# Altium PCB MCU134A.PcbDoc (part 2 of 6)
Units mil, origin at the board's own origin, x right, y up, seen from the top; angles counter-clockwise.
Board outline 4163.98 x 2693.8 mil, 6 copper layers (Top Layer, GND1, SIG1, PWR, GND2, Bottom), stack 58.132 mil thick; 218 components, 287 nets, 1260 pads, 770 vias.
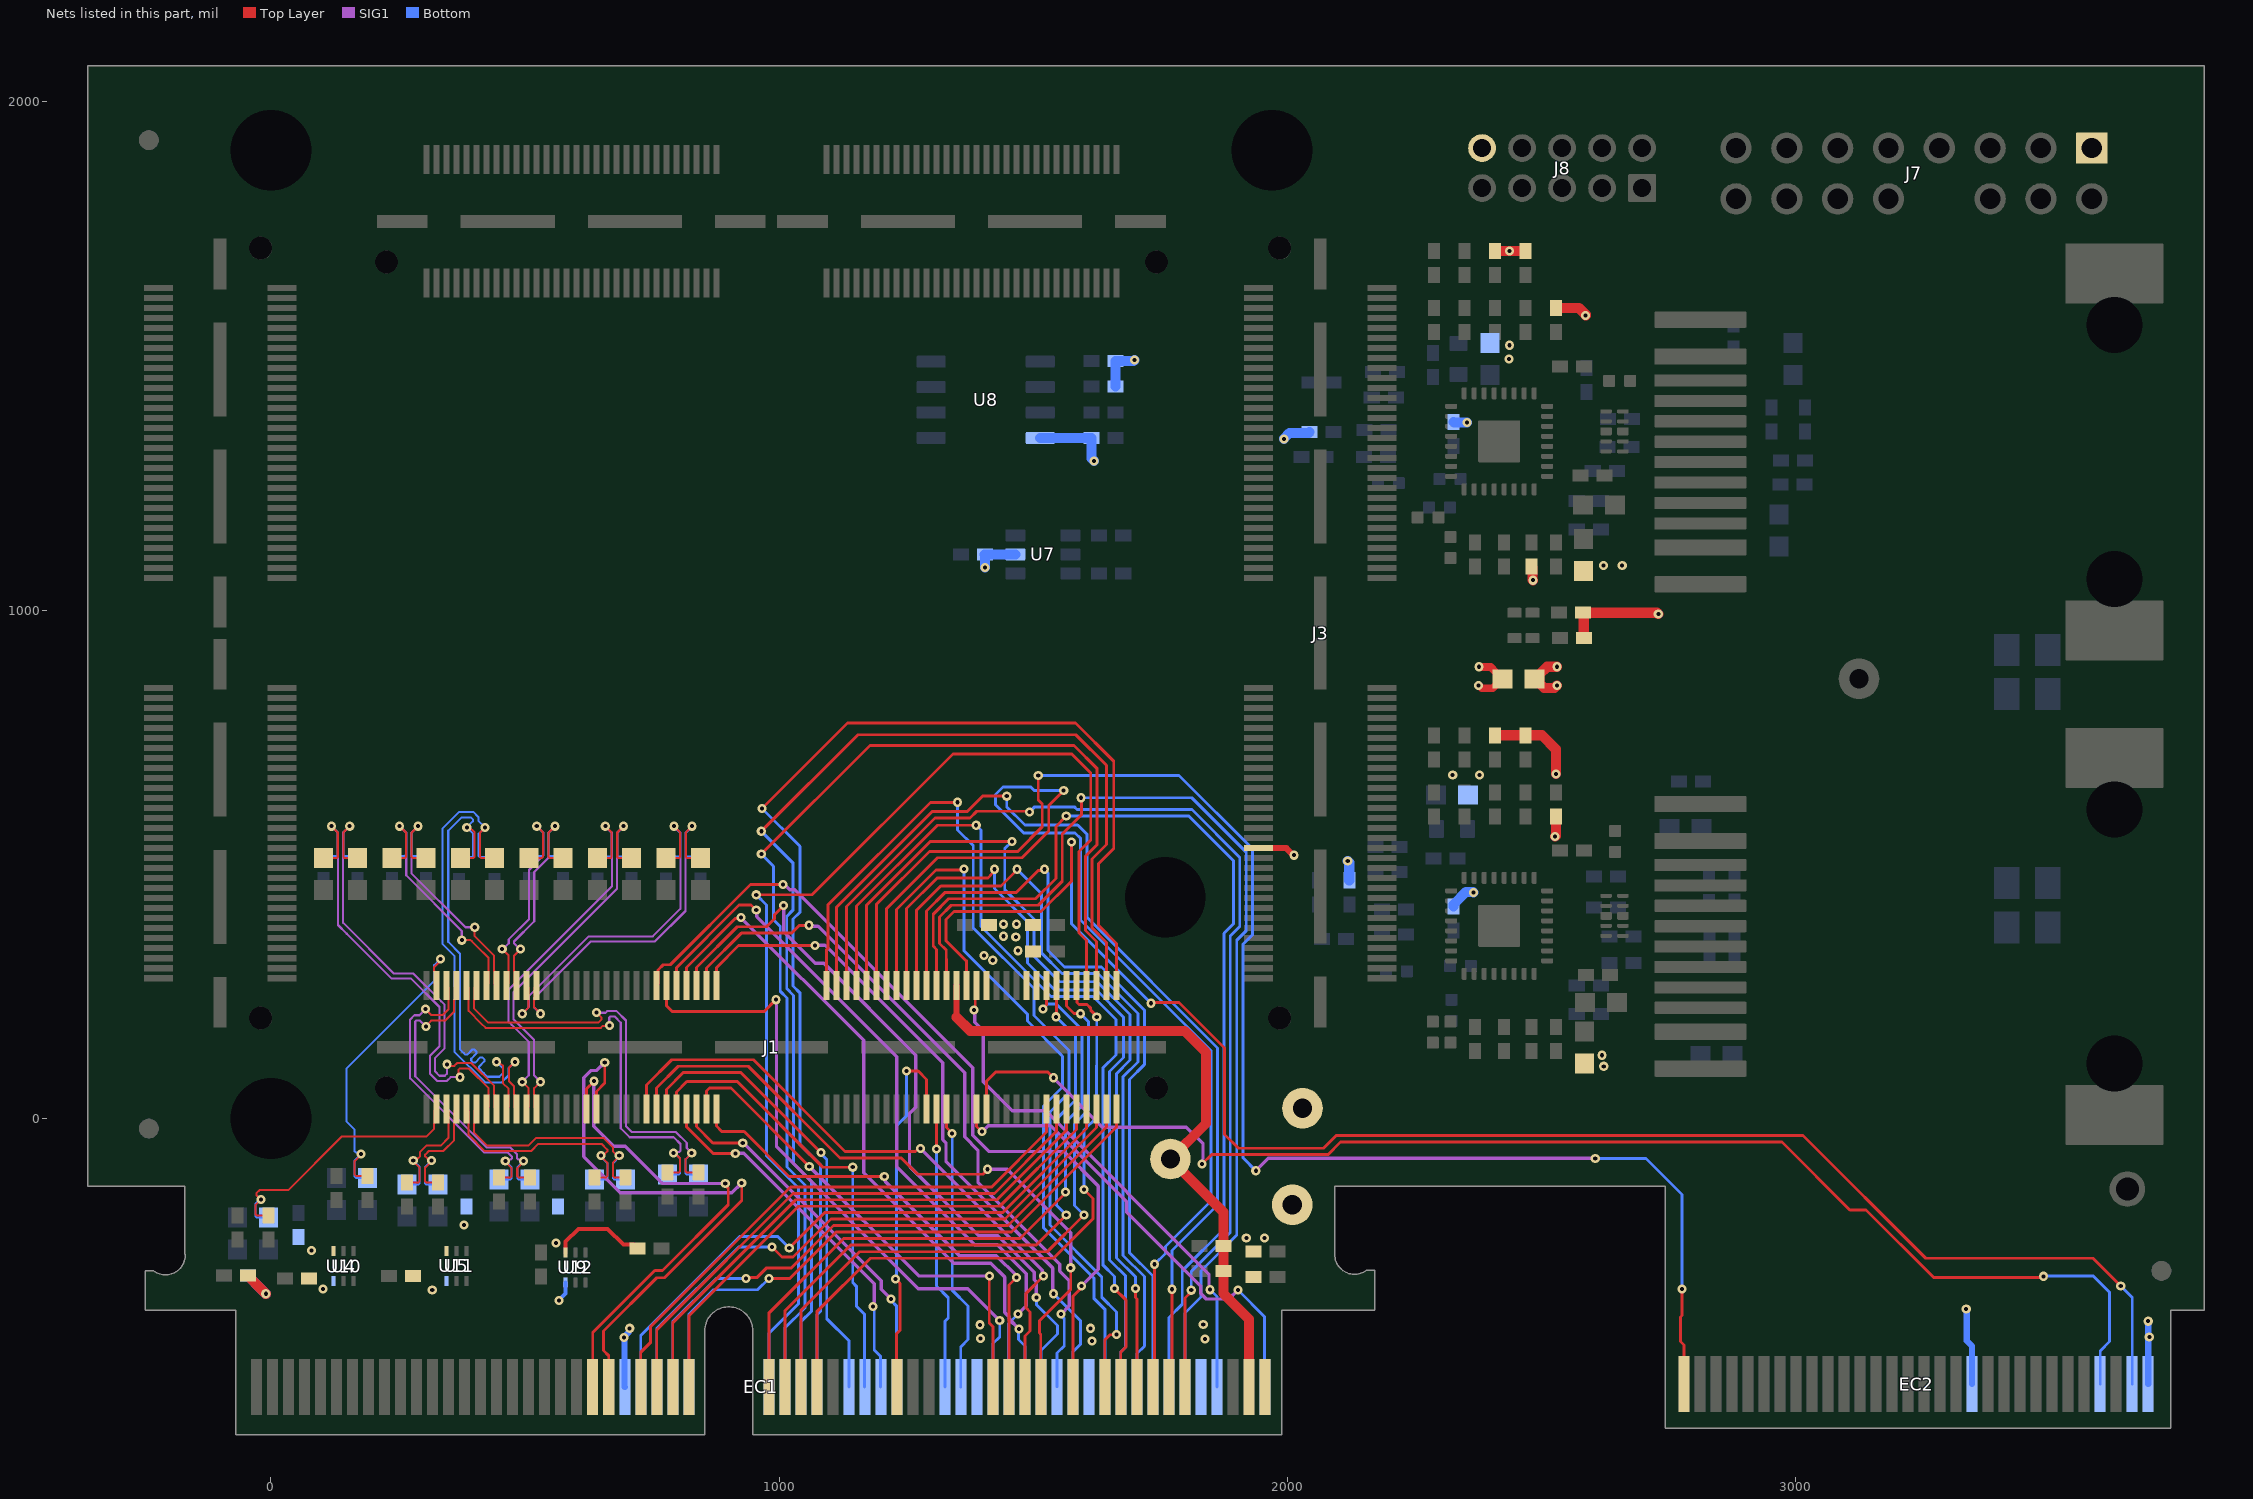
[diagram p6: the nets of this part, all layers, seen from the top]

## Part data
C1 C3 C9 C12 C13 C15 C18 C21 C23 C25 C26 C32 C33 C34 C35 C36 C37 C41 C48 C49 C60 C61: library part CMP-0006659-2, "CAP, CERM, 0.1 uF, 25 V, +/- 10%, X7R, 0402", Cap_Case=0402, Manufacturer=MuRata, Supplier Part Number 1=490-10698-1-ND, TempCo=X7R, Tolerance_%=10%, Value1=Unknown, Value2=25V, ValueDisplayed=0.1uF
C2 C10 C42 C50: library part CMP-0086061-1, "CAP, CERM, 1 µF, 25 V,+/- 10%, X5R, 0402", Cap_Case=0402, Manufacturer=MuRata, TempCo=X5R, Tolerance_%=10%, Value2=25V, ValueDisplayed=1µF
C4 C5 C6 C7 C43 C44 C45 C46: library part CMP-0006367-2, "CAP, CERM, 4.7 pF, 50 V, +/- 2%, C0G/NP0, 0402", Cap_Case=0402, Manufacturer=MuRata, Supplier Part Number 1=490-8102-1-ND, TempCo=C0G/NP0, Tolerance_%=2%, Value1=Unknown, Value2=50V, ValueDisplayed=4.7pF
C8 C47: library part CMP-0081010-1, "CAP, CERM, 2.2 µF, 25 V,+/- 20%, X5R, 0402", Cap_Case=0402, Manufacturer=MuRata, Supplier Part Number 1=490-10457-1-ND, TempCo=X5R, Tolerance_%=20%, Value2=25V, ValueDisplayed=2.2µF
C11 C16: library part CMP-0007324-5, "CAP, CERM, 22 uF, 10 V, +/- 20%, X5R, 0603", Cap_Case=0603, Manufacturer=MuRata, Supplier Part Number 1=490-10476-1-ND, TempCo=X5R, Tolerance_%=20%, Value1=Unknown, Value2=10V, ValueDisplayed=22uF
C14 C17: library part CMP-0120208-1, "Chip Multilayer Ceramic Capacitor for General Purpose 47uF ±20% 6.3V X5R SMD 0603", Digikey Part Number=490-GRM188R60J476ME01DCT-ND, Manufacturer=Murata, Mouser Part Number=81-GRM188R60J476ME01, Operating Temperature Range="-55°C to +85°C", TempCo=15%, Temperature Characteristic=X5R, Tolerance_%=20%, ValueDisplayed=47uF
C19 C59: library part CMP-0008156-2, "CAP, CERM, 0.01 uF, 50 V, +/- 5%, C0G/NP0, 0805", Cap_Case=0805, Manufacturer=MuRata, Supplier Part Number 1=490-1642-1-ND, TempCo=C0G/NP0, Tolerance_%=5%, Value1=Unknown, Value2=50V, ValueDisplayed=0.01uF
C20 C22 C24: library part CMP-0006564-3, "CAP, CERM, 10 uF, 10 V, +/- 20%, X5R, 0402", Cap_Case=0402, Manufacturer=MuRata, TempCo=X5R, Tolerance_%=20%, Value1=Unknown, Value2=10V, ValueDisplayed=10uF
C62 C63 C64 C65 C66 C67 C68 C69 C70 C71 C72 C73 C74 C75 C76 C77 C78 C79 C80 C81 C82 C83 C84 C85: library part CMP-0006823-4, "CAP, CERM, 330 pF, 50 V, +/- 5%, C0G/NP0, 0603", Cap_Case=0603, Manufacturer="Wurth Elektronik", Supplier Part Number 1=710-885012006060, TempCo=C0G/NP0, Tolerance_%=5%, Value1=Unknown, Value2=50V, ValueDisplayed=330pF
D1: library part CMP-0067681-2, "LED, Red, SMD", Color=Red, Manufacturer=Kingbright, Power_TotalModule=75mW, Value1=0.075W, Value2=1.95V
D2: library part CMP-0067682-2, "LED, Green, SMD", Color=Green, Manufacturer=Kingbright, Power_TotalModule=75mW, Value1=0.075W, Value2=2.1V
EC1: library part CMP-0003813-3, "C2000 controlCARD-120HSEC Edge Connector for Samtec HSEC8-160-01-L-DV-A-BL", Manufacturer=Any
EC2: library part CMP-0081961-1, "C2000 controlCARD-180HSEC (60-pin addon) Edge connector for Samtec HSEC8-130-01-L-DV-A", Manufacturer=Any
FID1 FID2 FID3 FID4 FID5 FID6: library part CMP-0077181-1, "Fiducial mark.  There is nothing to buy or mount.", Manufacturer=N/A
J1 J2 J3 J4: library part CMP-0056023-2, "Socket, 0.5MM, 60x2, Gold, SMT", Manufacturer=Samtec, Supplier Part Number 1=SAM8189-ND
J5 J11: library part CMP-0086350-1, "Connector, RJ45, 1x1, Gold, R/A, SMT", Manufacturer="Wurth Elektronik"
J7: library part CMP-0121702-1, "Connector Header Through Hole, Right Angle 16 position 0.100\" (2.54mm)", Digikey Part Number=612-TSW-108-08-G-D-RA-008-ND, Manufacturer=Samtec, Mouser Part Number=200-TSW10808GDRA008, Operating Temperature Range="-55°C to +125°C"
J8: library part CMP-0086568-1, "Board-To-Board Connector, TMM Series, 10 Contacts, Header, 2 mm, Through Hole, 2 Rows", Current_A=3.2A, Manufacturer=Samtec, Voltage_V=281V
Logo1: library part CMP-0074844-1
Logo2: library part CMP-0074838-1, "Texas Instrument Corporate Signature"
Logo3: library part CMP-0074847-1, "FCC_disclaimer"
Logo4: library part CMP-0074769-3, Manufacturer="Texas Instruments"
MH1 MH2 MH3 MH4: library part CMP-0078424-2, "PCB Mounting Hole, No Pad", Manufacturer=Any, PartNumber=N/A
R1 R2 R45 R46 R56 R57 R91 R92: library part CMP-0026631-1, "RES, 4.70 k, 1%, 0.063 W, 0402", Manufacturer="TE Connectivity", Power_W=63mW, Supplier Part Number 1=A121542CT-ND, TempCo="100 ppm/C", Tolerance_%=1%, Value2=0.063W, Value_Code=4k70, ValueDisplayed=4.70k
R3 R19 R26 R27 R58 R80 R81 R82: library part CMP-0026231-2, "RES, 2.20 k, 1%, 0.063 W, AEC-Q200 Grade 0, 0402", Manufacturer=Vishay-Dale, Power_W=63mW, Supplier Part Number 1=541-2.20KLCT-ND, TempCo="100 ppm/C", Tolerance_%=1%, Value2=0.063W, Value_Code=2k20, ValueDisplayed=2.20k
R4 R59: library part CMP-0026515-2, "RES, 6.49 k, 1%, 0.063 W, AEC-Q200 Grade 0, 0402", Manufacturer=Vishay-Dale, Power_W=63mW, Supplier Part Number 1=541-6.49KLCT-ND, TempCo="100 ppm/C", Tolerance_%=1%, Value2=0.063W, Value_Code=6k49, ValueDisplayed=6.49k
R5 R10 R11 R12 R14 R23 R32 R60 R65 R66 R67 R69: library part CMP-0001606-1, "RES Thick Film, 0Ω, 0.2W, 0402", Digikey Part Number=541-0.0YBCT-ND, Manufacturer="Vishay Dale", Mouser Part Number=71-CRCW04020000Z0EDH, Operating Temperature Range="-55°C to +155°C", Power_W=200mW
R6 R7 R8 R28 R29 R30 R31 R33 R61 R62 R63 R83 R84 R85 R86 R88: library part CMP-0026237-2, "RES, 2.49 k, 1%, 0.063 W, AEC-Q200 Grade 0, 0402", Manufacturer=Vishay-Dale, Power_W=63mW, Supplier Part Number 1=541-2.49KLCT-ND, TempCo="100 ppm/C", Tolerance_%=1%, Value2=0.063W, Value_Code=2k49, ValueDisplayed=2.49k
R9 R13 R15 R16 R17 R18 R20 R24 R64 R68 R70 R71 R72 R73 R74 R78: library part CMP-0026299-2, "RES, 33.2, 1%, 0.063 W, AEC-Q200 Grade 0, 0402", Manufacturer=Vishay-Dale, Power_W=63mW, Supplier Part Number 1=541-33.2LCT-ND, TempCo="100 ppm/C", Tolerance_%=1%, Value2=0.063W, Value_Code=33R2, ValueDisplayed=33.2
R21 R22 R35 R54 R55: library part CMP-0025874-4, "RES, 0, 5%, 0.1 W, AEC-Q200 Grade 0, 0603", Manufacturer=Panasonic, Power_W=100mW, Supplier Part Number 1=P0.0GCT-ND, TempCo="600 ppm/C", Tolerance_%=5%, Value2=0.1W, Value_Code=0000, ValueDisplayed=0
R25 R38 R79 R87: library part CMP-0025813-4, "RES, 470, 5%, 0.1 W, AEC-Q200 Grade 0, 0603", Manufacturer=Vishay-Dale, Power_W=100mW, Supplier Part Number 1=541-470GCT-ND, TempCo="200 ppm/C", Tolerance_%=5%, Value2=0.1W, Value_Code=470R, ValueDisplayed=470
R34 R89: library part CMP-0020623-3, "RES, 1.0 M, 5%, 0.125 W, AEC-Q200 Grade 0, 0805", Manufacturer=Panasonic, Power_W=125mW, Supplier Part Number 1=P1.0MACT-ND, TempCo="150 ppm/C", Tolerance_%=5%, Value2=0.125W, Value_Code=1M00, ValueDisplayed=1.0M
R36: library part CMP-0077731-1, "RES, 10.0 k, 1%, 0.063 W, AEC-Q200 Grade 0, 0402", Manufacturer="Yageo America", Power_W=63mW, Supplier Part Number 1=YAG3436CT-ND, TempCo="100 ppm/C", Tolerance_%=1%, Value2=0.063W, Value_Code=10k0, ValueDisplayed=10.0k
R90 R93: library part CMP-0026854-5, "RES, 1.2 k, 5%, 0.063 W, AEC-Q200 Grade 0, 0402", Manufacturer=Vishay-Dale, Power_W=63mW, Supplier Part Number 1=541-1.2KJCT-ND, TempCo="200 ppm/C", Tolerance_%=5%, Value2=0.063W, Value_Code=1k20, ValueDisplayed=1.2k
R94 R95: library part CMP-0026863-2, "RES, 1.5 M, 5%, 0.063 W, AEC-Q200 Grade 0, 0402", Manufacturer=Vishay-Dale, Power_W=63mW, Supplier Part Number 1=541-1.5MJCT-ND, TempCo="200 ppm/C", Tolerance_%=5%, Value2=0.063W, Value_Code=1M50, ValueDisplayed=1.5M
R96 R97 R98 R99 R100 R101 R102 R103 R104 R105 R106 R107 R108 R109 R110 R111 R112 R113 R114 R115 R116 R117 R118 R119 R120: library part CMP-0026822-3, "RES, 0, 5%, 0.063 W, AEC-Q200 Grade 0, 0402", Manufacturer=Vishay-Dale, Power_W=63mW, Supplier Part Number 1=541-0.0JCT-ND, TempCo="200 ppm/C", Tolerance_%=5%, Value2=0.063W, Value_Code=0000, ValueDisplayed=0
TP1 TP2 TP3 TP4: "TEST POINT.  No entry in BOM.", Manufacturer=N/A
U1 U3: library part CMP-0001411-1, "Ethernet PHY 10BASE-Te/00BASE-TX 10/100 Mbps 160mW 1.8V/3.3V 2-Pin VQFN Industrial", Digikey Part Number=296-DP83826IRHBRCT-ND, Manufacturer="Texas Instruments", Max Supply Voltage=3.6V, Min Supply Voltage=1.62V, Mouser Part Number=595-DP83826IRHBR, Operating Temperature Range="-40°C to +85°C"
U2 U6: library part CMP-0073613-3, "4-Channel Ultra-Low-Capacitance IEC ESD Protection Diode, DQA0010A (USON-10)", Alternate Manufacturer="Texas Instruments"
U4 U5 U9 U10 U11 U12: library part CMP-0043110-1, "Low-Capacitance + / - 15-kV ESD Protection Array for High-Speed Data Interfaces, 4 Channels, -40 to +85 degC, 6-pin USON (DPK), Green (RoHS & no Sb/Br)", Breakdown Voltage(Min)(V)=11, IO Capacitance(Typ)(pF)=1.5, Manufacturer="Texas Instruments"
U7: library part CMP-0051777-2, "Dual Inverter Buffer/Driver with Open-Drain Output, DBV0006A, LARGE T&R", F @ Nom Voltage(Max)(Mhz)=150, Generic Part Number=SN74LVC2G06, ICC @ Nom Voltage(Max)(mA)=0.01, Manufacturer="Texas Instruments", Operating Temperature Range(C)="-40 to 125,-40 to 85", Rating=Catalog, tpd @ Nom Voltage(Max)(ns)=8.2,4.4,3.9,3.4, Voltage(Nom)(V)=1.8,2.5,3.3,5
U8: library part CMP-0082059-1, "16 Kb I2C EEPROM Serial, SOIC-8", Manufacturer="ON Semiconductor", Supplier Part Number 1=CAT24C16WI-GT3CT-ND
ZZ1: library part CMP-0003616-3
ZZ2: library part CMP-0077236-1
ZZ3: library part CMP-0077237-1
ZZ4: library part CMP-0077238-1

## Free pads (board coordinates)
  round 70 hole 45: 6(3653,-139)

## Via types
v1: diameter 18, hole 8, Top Layer to Bottom, tented both sides, 761 vias
v2: diameter 19.68, hole 7.87, Top Layer to Bottom, tented both sides, 9 vias

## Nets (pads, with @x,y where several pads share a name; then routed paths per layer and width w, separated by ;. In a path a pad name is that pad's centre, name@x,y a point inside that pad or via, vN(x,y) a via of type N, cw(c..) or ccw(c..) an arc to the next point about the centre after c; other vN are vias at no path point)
3V3_ETH: C60.1 C61.1 R2.1 R3.2 R6.2 R7.2 R8.2 R19.2 R21.2 R22.1 R35.2 R54.2 R55.1 R57.1 R58.1 R61.2 R62.2 R63.2 R90.1 R91.2 R92.2 R93.1 U7.5 U8.8 | length 1180.9
  Top Layer w20: R63.2@2406.66,755.65 R63.2@2408.47,753.84 R62.2@2468.47,753.84 2501.16,753.84 2528.47,726.53 v1@2528.47,678 ; R8.2@2408.47,1707.12 2408.59,1707 v1(2437,1707) 2468.35,1707 R7.2@2468.47,1707.12 ; R19.2@2480.52,1086.01 2482.33,1084.2 2482.33,1060 v1(2483.29,1059.04) ; R35.2@2486.5,865 2487.3,865 2496,856.3 2496.18,856.3 2505.48,847 2525.87,847 v1(2531,852.13) ; R35.2@2496,864 2496,873.52 2511.27,888.79 v1(2531,888.79) ; v1(2526.66,554.53) 2528.47,556.34 R58.1@2528.47,594.35 ; R3.2@2528.47,1594.88 2573.46,1594.88 2587.09,1581.25 v1(2587.09,1580.07) ; R90.1@2581.5,995 R90.1@2581.65,995 ; R93.1@2583.46,945 2583.46,993.19 R90.1@2581.65,995 ; v1(2730,992.67) 2727.67,995 R90.1@2581.65,995
  Bottom w20: v1(1404.91,1083.69) 1404.91,1109.69 C61.1@1404.8,1109.81 U7.5@1464.8,1109.81 ; U8.8@1513.88,1339.03 C60.1@1614.97,1339.03 1614.97,1298.73 v1(1619.97,1293.73) ; R91.2@1662.22,1440.03 R92.2@1662.22,1490.03 1697.24,1490.03 v1(1699.54,1492.33) ; v1(1993.39,1336.95) 1993.39,1337.88 2004.13,1348.61 2042.13,1348.61 R6.2@2043.94,1350.43 ; v1(2119,506.37) 2122,503.37 R61.2@2122,468.62 ; R57.1@2326.96,417.02 2326.96,420.95 2351.72,445.72 2365.11,445.72 v1(2366.15,444.67) ; R2.1@2327.18,1370.53 2328.66,1369.05 v1(2353.29,1369.05)
  other v1: 2622.7,102.54 2619.1,124.25 2325.41,675.99 2378,675.99 2529,678 2622,1088 2659,1088 2436.01,1494.09 2436.9,1521.28
3V3_OUT: C22.1 C23.1 C32.1 C33.1 C34.1 C35.1 C36.1 C37.1 EC1.119 J1.28 J7.1 J8.10 R35.1 R45.2 R46.2 TP2.1 U4.6 U5.6 U9.6 U10.6 U11.6 U12.6 | length 448
  Top Layer w8: U9.6@579.66,-263.61 579.66,-242.55 605,-217.21 662.64,-217.21 693.47,-248.04 713.42,-248.04 C37.1@721.22,-255.84
  Top Layer w15: v1(2376,851.97) 2376.81,851.97 2382.48,846.3 2403.82,846.3 R35.1@2422.52,865 ; v1(2377,888.79) 2377.57,888.21 2400.29,888.21 2411.32,877.19 2411.32,876.2 R35.1@2422.52,865 ; R35.1@2423.5,865 R35.1@2422.52,865
  Top Layer w20: R45.2@-45,-310 -40.45,-310 -39.25,-311.2 -39.25,-315.75 -30,-325 -30,-325.36 -10.36,-345 v1(-10,-345)
  Bottom w8: v1(567,-358) 567,-357.17 579.66,-344.5 U12.6@579.66,-322.66
  Bottom w20: R46.2@-45,-310 -40.45,-310 -39.25,-311.2 -39.25,-315.75 -30,-325 -30,-325.36 -10.36,-345 v1(-10,-345)
  other v1: 317.52,-337.52 102.28,-335.36 80,-260 561,-244.94 1919.34,-235 1955,-235 380,-210 1420.39,311.2 1403.43,320.35
5V0_IN: C20.1 C21.1 EC1.48 EC1.84 EC1.98 EC1.112 EC2.158 EC2.180 J1.18 J1.20 J3.27 R36.2 TP1.1 | length 474.2
  Top Layer w12: J3.27@1943.5,531.77 1997.99,531.77 2011.88,517.88 v1(2013.5,517.88)
  Bottom w12: EC1.48@696.32,-528.32 695.66,-527.66 695.66,-431.66 v1(695,-431) 695,-429.38 704.85,-419.52 704.85,-414.15 v1(706,-413) ; v1(3335.81,-374.84) 3336.96,-375.98 3336.96,-437.51 3347.56,-448.11 EC2.158@3347.56,-522.97 ; EC2.180@3694.02,-522.97 3694.01,-433.62 3696.16,-431.47 v1(3696.16,-429.84) ; v1@3694,-430 v1(3694,-399)
  other v1: 1616,-438 1838.39,-434.18 1396,-433 1613,-413 1395.34,-406.09 1834.62,-405.78 1470.03,330.03 1465.79,356.71 1441.68,358.38 1441.24,382.12 1467.1,382.12
5V0_OUT_CAN: C24.1 C26.1 EC1.117 J1.34 TP3.1 | length 1333.2
  Top Layer w12: 1349.17,199.14 J1.34@1349.17,261.5
  Top Layer w20: 1349.17,199.14 1376.03,172.28 1797.72,172.28 1840,130 1840,-10 TP3.1@1770,-80 1874.49,-184.49 C24.1@1874.49,-251.43 C26.1@1874.49,-300.54 1874.49,-344.84 1924.67,-395.02 EC1.117@1924.67,-528.32
CON1_PIN1: EC1.56 J1.1 | length 1172.3
  Top Layer w5.66: v1(980,-315) 1021.02,-315 1112.58,-223.44 1457.56,-223.44 1664.13,-16.87 J1.1@1664.13,18.5
  Bottom w5.66: EC1.56@822.31,-528.32 822.31,-386.28 871.36,-337.22 957.78,-337.22 v1(980,-315)
CON1_PIN2: EC1.64 J1.2 | length 2461.2
  Top Layer w5.66: v1(966.36,610) 1134.36,778 1583,778 1658.4,702.6 1658.4,530.88 1628.17,500.65 1628.17,380.39 1664.13,344.43 J1.2@1664.13,261.5
  Bottom w5.66: v1(966.36,610) 1041,535.36 1041,405.52 1027.62,392.14 1027.62,260.58 1040.81,247.38 1040.81,-50.85 1081.18,-91.21 1081.18,-379.73 1074.27,-386.63 EC1.64@1074.27,-528.32
CON1_PIN3: EC1.54 J1.3 | length 1176.1
  Top Layer w5.66: v1(935,-315) 937.27,-312.73 957.06,-312.73 975.78,-294 1024.12,-294 1107.34,-210.78 1450.54,-210.78 1644.45,-16.87 J1.3@1644.45,18.5
  Bottom w5.66: EC1.54@790.81,-528.32 790.81,-399.87 875.68,-315 v1(935,-315)
CON1_PIN4: EC1.62 J1.4 | length 2392.4
  Top Layer w5.66: v1(965,565) 1155,755 1583.76,755 1644,694.76 1644,539 1615.51,510.51 1615.51,375.15 1644.45,346.21 J1.4@1644.45,261.5
  Bottom w5.66: v1(965,565) 1027,503 1027,409.43 1014.96,397.38 1014.96,255.33 1028.15,242.13 1028.15,-88.62 1063.54,-124 1063.54,-379.46 1042.78,-400.22 EC1.62@1042.78,-528.32
CON1_PIN5: EC1.52 J1.5 | length 1197.2
  Top Layer w5.66: v1(985.84,-252.89) 1005.77,-272.83 1027.39,-272.83 1102.09,-198.12 1444.69,-198.12 1624.76,-18.05 J1.5@1624.76,18.5
  Bottom w5.66: EC1.52@759.31,-528.32 759.31,-413.46 919.88,-252.89 v1(985.84,-252.89)
CON1_PIN6: EC1.60 J1.6 | length 2314.1
  Top Layer w5.66: v1(965,520) 1179,734 1580,734 1625.91,688.09 1625.91,538.81 1602.85,515.75 1602.85,369.91 1624.76,347.99 J1.6@1624.76,261.5
  Bottom w5.66: v1(965,520) 989,496 989,391 1002.3,377.7 1002.3,250.09 1015.49,236.89 1015.49,-95.49 1050.88,-130.88 1050.88,-373.12 1011.28,-412.72 EC1.60@1011.28,-528.32
CON1_PIN7: EC1.50 J1.7 | length 1204.6
  Top Layer w5.66: v1(1020,-255) 1089.54,-185.46 1439.45,-185.46 1605.08,-19.83 J1.7@1605.08,18.5
  Bottom w5.66: EC1.50@727.82,-528.32 727.82,-427.05 922.87,-232 997,-232 v1(1020,-255)
CON1_PIN8: EC1.58 J1.8 | length 2249.4
  Top Layer w5.66: v1(955,440) 1065,440 1342,717 1576,717 1613.25,679.75 1613.25,548 1590.19,524.94 1590.19,364.66 1605.08,349.77 J1.8@1605.08,261.5
  Bottom w5.66: v1(955,440) 975.26,419.74 975.26,-74.26 1038.22,-137.22 1038.22,-364.78 979.79,-423.21 EC1.58@979.79,-528.32
CON1_PIN9: EC1.55 J1.9 | length 1094.6
  Top Layer w5.66: EC1.55@822.57,-528.06 822.57,-388.33 1038.09,-172.8 1434.2,-172.8 1585.39,-21.61 J1.9@1585.39,18.5
CON1_PIN10: EC1.63 J1.10 | length 1269.5
  Top Layer w5.66: EC1.63@1074.27,-528.32 1074.27,-380.51 1179.63,-275.16 1540.06,-275.16 1617.83,-197.39 1617.83,-157.83 v1(1600,-140) ; J1.10@1585.39,261.5 1586.39,260.5 1586.39,227.78 1590.31,223.86 1606.14,223.86 1613.3,216.7 1613.3,212.7 1625,201 v1(1625,199.67)
  Bottom w5.66: v1(1600,-140) 1600,-23 1624.34,1.34 1624.34,104.24 1625,104.9 v1(1625,199.67)
CON1_PIN11: EC1.53 J1.11 | length 1099.8
  Top Layer w5.66: EC1.53@790.81,-528.32 790.81,-402.18 1032.85,-160.14 1428.96,-160.14 1565.71,-23.39 J1.11@1565.71,18.5
CON1_PIN12: EC1.61 J1.12 | length 1280.9
  Top Layer w5.66: EC1.61@1042.78,-528.32 1042.78,-377.78 1158.3,-262.26 1527.74,-262.26 v1(1600,-190) ; J1.12@1565.71,261.5 1565.71,221.13 1580.15,206.69 1592.24,206.69 v1(1592.9,206.03)
  Bottom w5.66: v1(1592.9,206.03) 1608.47,190.46 1608.47,16.47 1581.17,-10.83 1581.17,-171.17 v1(1600,-190)
CON1_PIN13: EC1.51 J1.13 | length 1104.7
  Top Layer w5.66: EC1.51@759.31,-528.32 759.31,-416.15 766.97,-408.49 766.97,-408.12 1027.61,-147.48 1423.71,-147.48 1546.02,-25.18 J1.13@1546.02,18.5
CON1_PIN14: EC1.59 J1.14 | length 1272.7
  Top Layer w5.66: EC1.59@1011.28,-528.32 1011.28,-378.72 1141.24,-248.76 1506.24,-248.76 v1(1565,-190) ; v1(1545.17,199.94) 1545.6,200.37 1545.6,261.07 J1.14@1546.02,261.5
  Bottom w5.66: v1(1545.17,199.94) 1583.15,161.96 1583.15,36.15 1545.51,-1.49 1545.51,-170.51 v1(1565,-190)
CON1_PIN15: EC1.49 J1.15 | length 1109.6
  Top Layer w5.66: EC1.49@727.82,-528.32 727.82,-460.18 746.65,-441.35 746.65,-410.53 1022.36,-134.82 1418.47,-134.82 1526.34,-26.96 J1.15@1526.34,18.5
CON1_PIN16: EC1.57 J1.16 | length 1312.1
  Top Layer w5.66: EC1.57@979.79,-528.32 979.79,-383.5 1127.19,-236.1 1473.9,-236.1 1563.34,-146.66 v1(1563.34,-145) ; v1(1519.1,215.19) 1519.1,216.3 1526.34,223.54 J1.16@1526.34,261.5
  Bottom w5.66: v1(1519.1,215.19) 1528.91,225 1545.32,225 1595.81,174.51 1595.81,24.81 1563.34,-7.66 v1(1563.34,-145)
CON1_PIN27: EC2.174 J1.27 | length 2705.8
  Top Layer w5.66: J1.27@1407.9,18.84 1407.9,73.11 1426.2,91.41 1528.59,91.41 v1(1540,80) ; v1(1832.04,-90) 1850.7,-71.34 2079.91,-71.34 2104.92,-46.33 2973.31,-46.33 3106.89,-179.91 3138.96,-179.91 3271.88,-312.83 3486.17,-312.83 v1(3488.29,-310.71)
  SIG1 w6.66: v1(1540,80) 1540,78.68 1636.26,-17.58 1801.58,-17.58 1834.21,-50.21 1834.21,-87.83 v1(1832.04,-90)
  Bottom w5.66: v1(3488.29,-310.71) 3489,-310 3586,-310 3618,-342 3618,-439 3599.53,-457.47 EC2.174@3599.53,-522.97
CON1_PIN29: EC1.120 J1.29 | length 939.3
  Top Layer w5.66: J1.29@1388.54,18.5 1388.62,18.42 1388.62,-15.8 1398.64,-25.82 v1(1399.58,-25.82)
  SIG1 w6.66: v1(1399.58,-25.82) 1411.3,-14.1 1534.1,-14.1 1683.83,-163.83 1683.83,-184.9 1829.33,-330.41 1829.33,-344.25 1840.41,-355.33 1885.1,-355.33 v1(1902.72,-337.72)
  Bottom w5.66: v1(1902.72,-337.72) 1955.25,-390.25 1955.25,-527.41 EC1.120@1956.16,-528.32
CON1_PIN30: EC1.114 J1.30 | length 1028
  Top Layer w5.66: v1(1383.71,213.23) 1386.07,215.59 1386.07,259.02 J1.30@1388.54,261.5
  SIG1 w6.66: v1(1383.71,213.23) 1385,211.93 1385,189 1402,172 1402,72.08 1459.08,15 1524.32,15 1845.83,-306.51 1845.83,-334.83 v1(1848,-337)
  Bottom w5.66: v1(1848,-337) 1861.68,-350.68 EC1.114@1861.68,-528.32
CON1_PIN32: EC2.178 J1.32 | length 3346.9
  Top Layer w5.66: J1.32@1368.86,261.5 1368.86,310.14 1367.98,310.14 1328.58,349.55 1328.58,391.34 1344.12,406.88 1515.26,406.88 1575.11,466.73 v1(1575.11,543.96) ; v1(1731.6,226.6) 1732.96,227.96 1787.04,227.96 1876.41,138.59 1876.41,-31.41 1903.68,-58.68 2071.32,-58.68 2096.33,-33.67 3014.72,-33.67 3256.22,-275.17 3585.17,-275.17 v1(3640,-330)
  Bottom w5.66: v1(1575.11,543.96) 1575.11,383.09 v1(1731.6,226.6) ; v1(3640,-330) 3662.52,-352.52 EC2.178@3662.52,-522.97
CON1_PIN35: EC1.82 J1.35 | length 570.7
  Top Layer w5.66: J1.35@1329.49,18.5 1329.48,-18.13 1340,-28.65 v1(1340,-30)
  Bottom w5.66: v1(1340,-30) 1340.64,-30.64 1340.64,-338.17 1371.72,-369.25 1371.72,-435.28 1357.33,-449.67 EC1.82@1357.33,-528.73
CON1_PIN36: EC1.110 J1.36 | length 2062.4
  Top Layer w5.66: J1.36@1329.49,261.5 1329.49,313.28 1329.02,313.75 1329.02,331.2 1315.92,344.3 1315.92,396.58 1338.88,419.54 1510.01,419.54 1557.28,466.8 1557.28,559.67 1595,597.4 1595,630.32 v1(1594.37,630.95)
  Bottom w5.66: v1(1594.37,630.95) 1812.05,630.95 1919.18,523.82 1919.18,369.18 1900.51,350.51 1900.51,-229.72 1830.17,-300.06 1830.17,-351.21 1798.68,-382.7 EC1.110@1798.68,-528.32
CON1_PIN37: EC1.80 J1.37 | length 559.1
  Top Layer w5.66: J1.37@1309.8,18.5 1309.9,18.4 1309.9,-59.9 v1(1310,-60)
  Bottom w5.66: v1(1310,-60) 1310,-330 1332.83,-352.83 1332.83,-392.61 1326.24,-399.2 EC1.80@1326.24,-528.32
CON1_PIN38: EC1.108 J1.38 | length 1998.1
  Top Layer w5.66: J1.38@1309.8,261.5 1309.8,332.51 1303.26,339.06 1303.26,401.82 1333.63,432.2 1504.77,432.2 1544.62,472.05 1544.62,574.62 v1(1565,595)
  Bottom w5.66: v1(1565,595) 1806,595 1893.86,507.14 1893.86,382.86 1875.19,364.19 1875.19,-217.81 1793.17,-299.83 1793.17,-365.83 1767.19,-391.81 EC1.108@1767.19,-528.32
CON1_PIN39: EC1.73 J1.39 | length 741.8
  Top Layer w5.66: v1(1228.95,-316.05) 1229.39,-316.05 1237.83,-324.49 1237.83,-416.95 1231.16,-423.63 1231.16,-527.73 EC1.73@1231.75,-528.32 ; v1(1250.46,93.03) 1273.66,93.03 1289.94,76.75 1289.94,18.67 J1.39@1290.12,18.5
  Bottom w5.66: v1(1228.95,-316.05) 1230.83,-314.17 1230.83,-14.34 1250.46,5.3 v1(1250.46,93.03)
CON1_PIN40: EC1.106 J1.40 | length 1586.3
  Top Layer w5.66: J1.40@1290.36,261.25 1290.36,408.42 1326.8,444.86 1466.86,444.86 1509.97,487.97 1519.64,487.97 v1(1522,490.33)
  Bottom w5.66: v1(1522,490.33) 1529.33,483 1529.33,330.57 1561.9,298 1634.28,298 1718.66,213.62 1718.66,105.76 1689.66,76.76 1689.66,-264.29 1735.69,-310.32 EC1.106@1735.69,-528.32
CON1_PIN42: EC1.104 J1.42 | length 1574
  Top Layer w5.66: J1.42@1270.43,261.5 1270.43,409.69 1318.26,457.52 1436.52,457.52 1468,489 v1(1468,490.33)
  Bottom w5.66: v1(1468,490.33) 1516,442.33 1516,326 1556.66,285.34 1627.39,285.34 1706,206.73 1706,111 1677,82 1677,-269.53 1718.83,-311.36 1718.83,-448.17 1704.2,-462.8 EC1.104@1704.2,-528.32
CON1_PIN44: EC1.102 J1.44 | length 1560.2
  Top Layer w5.66: J1.44@1250.75,261.5 1250.75,412.78 1311.14,473.17 1411.06,473.17 1415.76,477.87 1415.76,478.75 1424,486.99 v1(1424,490.33)
  Bottom w5.66: v1(1424,490.33) 1424,452.1 1489,387.1 1489,306 1542.34,252.66 1624.26,252.66 1677.99,198.93 1677.99,119.99 1650,92 1650,-278.34 1681.97,-310.31 1681.97,-449.86 1672.29,-459.54 EC1.102@1672.29,-528.73
CON1_PIN46: EC1.100 J1.46 | length 1480.8
  Top Layer w5.66: J1.46@1231.06,261.5 1231.06,411 1308.7,488.64 1361.64,488.64 v1(1364,491)
  Bottom w5.66: v1(1364,491) 1364,329.76 1488.45,205.32 1488.61,205.32 1488.61,191.39 1557.83,122.17 1557.83,61.83 1520.19,24.19 1520.19,-215.15 1620,-314.96 1620,-354.78 1641.61,-376.4 EC1.100@1641.61,-527.92
CON1_PIN48: EC1.105 J1.48 | length 2216.1
  Top Layer w5.66: J1.48@1211.38,261.5 1211.38,412.67 1311.54,512.83 1477.83,512.83 1530.49,565.49 1530.49,615.49 v1(1560,645) ; EC1.105@1735.69,-528.32 1739,-525.01 v1(1739,-287)
  Bottom w5.66: v1(1560,645) 1502.05,645 1495.17,651.88 1440.56,651.88 1425.82,637.13 1425.82,617.28 1481.31,561.79 1582.49,561.79 1592.94,551.34 1592.94,390.48 1849.87,133.54 1849.87,-162.2 1760.17,-251.9 1760.17,-265.83 v1(1739,-287)
CON1_PIN50: EC2.121 J1.50 | length 3041.8
  Top Layer w5.66: J1.50@1191.96,261.76 1191.96,421.52 1295.94,525.49 1469.49,525.49 1517.83,573.83 1517.83,618.83 1510,626.66 v1(1510,675) ; v1(2776.82,-336) 2776.82,-387.69 2773.83,-390.68 2773.83,-439.03 2780.63,-445.83 EC2.121@2780.63,-522.97
  SIG1 w6.66: v1(1938,-103) 1962.35,-78.65 v1(2606,-78.65)
  Bottom w5.66: v1(1510,675) 1787,675 1931.84,530.16 1931.84,361.84 1913.17,343.17 1913.17,-78.17 v1(1938,-103) ; v1(2606,-78.65) 2705.74,-78.65 2776.82,-149.72 2776.82,-261.43 v1(2776.82,-336)
CON1_PIN52: EC1.103 J1.52 | length 1748.4
  Top Layer w5.66: J1.52@1172.01,261.5 1172.01,419.47 1297.54,545 v1(1458,545) ; v1(1701,-335) 1701.37,-335.37 1701.37,-352.49 1704.2,-355.32 EC1.103@1704.2,-528.32
  Bottom w5.66: v1(1458,545) 1444,531 1444,450 1501.66,392.34 1501.66,319 1551.66,269 1625.82,269 1690.65,204.17 1690.65,114.65 1664,88 1664,-274.44 1701,-311.44 v1(1701,-335)
CON1_PIN54: EC1.101 J1.54 | length 1759.6
  Top Layer w5.66: J1.54@1152.32,261.66 1152.32,417.69 1311.57,576.94 v1@1387.8,576.94 ; v1(1660,-335) 1682.95,-357.95 1682.95,-448.71 1672.29,-459.37 EC1.101@1672.29,-528.73
  Bottom w5.66: v1(1387.85,576.89) 1397,567.74 1397,377.85 1534.85,240 1617.62,240 1662.83,194.79 1662.83,124.83 1637,99 1637,-288 1660,-311 v1(1660,-335)
CON1_PIN56: EC1.109 J1.56 | length 2139.7
  Top Layer w5.66: J1.56@1132.64,261.5 1132.64,417.16 1306.61,591.13 1375.47,591.13 1388.81,604.47 1491.53,604.47 v1(1493,603) ; EC1.109@1798.68,-528.32 1798.68,-353.66 1811,-341.34 v1(1811,-338)
  Bottom w5.66: v1(1493,603) 1503.12,613.12 1580.88,613.12 1586.34,607.66 1812.34,607.66 1906.52,513.48 1906.52,377.52 1887.85,358.85 1887.85,-224.48 1811,-301.33 v1(1811,-338)
CON1_PIN58: EC1.107 J1.58 | length 2013.5
  Top Layer w5.66: J1.58@1113.16,261.7 1113.16,415.59 1301.8,604.23 1370.66,604.23 1400.48,634.05 v1(1447.95,634.05) ; EC1.107@1767.19,-528.32 1772.83,-522.68 v1(1772.83,-336.19)
  Bottom w5.66: v1(1447.95,634.05) 1447.95,613.05 1483.83,577.17 1587.54,577.17 1605.6,559.12 1605.6,395.72 1862.53,138.79 1862.53,-170.47 1772.83,-260.17 v1(1772.83,-336.19)
CON1_PIN60: EC1.99 J1.60 | length 1827.1
  Top Layer w5.66: J1.60@1093.27,261.5 1093.27,331.78 1095.9,334.41 1095.9,419.68 1297.64,621.42 1350.47,621.42 v1(1351.11,622.06) ; EC1.99@1640.8,-528.73 1640.8,-435.96 1651.02,-425.73 1663.84,-425.73 v1(1664.14,-425.43)
  Bottom w5.66: v1(1351.11,622.06) 1351.11,567.78 1382,536.89 1382,374.94 1501.27,255.67 1501.27,202.6 1570.49,133.38 1570.49,50.49 1532.85,12.85 1532.85,-209.91 1635,-312.06 1635,-351.88 1664.14,-381.02 v1(1664.14,-425.43)
CON1_PIN61: EC1.87 J1.61 | length 975.8
  Top Layer w5.66: J1.61@876.73,18.5 876.73,-15.24 887.27,-25.77 931.3,-25.77 1019.53,-114 v1(1207,-114) ; EC1.87@1452.23,-528.32 1452.23,-426.85 1452.17,-426.8 1452.17,-327.83 v1(1467.22,-312.78)
  SIG1 w6.66: v1(1207,-114) 1209.17,-116.17 1209.17,-124.17 1355,-270 1427.51,-270 1467.22,-309.71 v1(1467.22,-312.78)
CON1_PIN62: EC1.96 J1.62 | length 1350.9
  Top Layer w5.66: J1.62@876.73,261.5 876.73,296.39 920.34,340 1070.34,340 v1(1070.83,340.49)
  SIG1 w6.66: v1(1070.83,340.49) 1090.43,340.49 1321.67,109.25 1321.67,-41.57 1328.33,-48.23 1328.33,-84.01 1538.65,-294.33 1538.65,-343.65 v1(1540,-345)
  Bottom w5.66: v1(1540,-345) 1593.43,-398.43 1593.43,-444.16 1577.8,-459.79 EC1.96@1577.8,-528.73
CON1_PIN63: EC1.85 J1.63 | length 969.6
  Top Layer w5.66: J1.63@857.05,18.5 857.05,53.88 862.85,59.68 905.32,59.68 1059.38,-94.38 v1(1059.38,-94.62) ; v1(1414,-310) 1413.42,-310.58 1413.42,-402.44 1420.76,-409.78 EC1.85@1420.76,-528.3
  SIG1 w6.66: v1(1059.38,-94.62) 1274.75,-310 v1(1414,-310)
CON1_PIN64: EC1.94 J1.64 | length 1415.1
  Top Layer w5.66: J1.64@857.05,261.5 857.05,295.86 925.7,364.51 1024.51,364.51 1039.63,379.63 1058.23,379.63 v1(1058.64,380.05)
  SIG1 w6.66: v1(1058.64,380.05) 1060.81,377.88 1076.63,377.88 1365,89.51 1365,-36.48 1391.34,-62.82 1391.34,-125.66 1552.31,-286.63 1552.31,-300.31 1571,-319 1571,-369 v1@1555,-385
  Bottom w5.66: EC1.94@1547.12,-527.92 1547.12,-461.71 1561,-447.83 1561,-394.34 1554.89,-388.23 v1(1554.89,-385.11)
CON1_PIN65: EC1.74 J1.65 | length 744.7
  Top Layer w5.66: J1.65@837.4,18.47 837.4,-15.97 869.64,-48.21 v1(928.52,-48.21)
  SIG1 w6.66: v1(928.52,-48.21) 929.53,-48.21 1200.84,-319.53 1200.84,-335.84 v1(1220,-355)
  Bottom w5.66: v1(1220,-355) 1220,-358.34 1231.38,-369.72 EC1.74@1231.38,-527.95
CON1_PIN66: EC1.92 J1.66 | length 1488.5
  Top Layer w5.66: J1.66@837.36,261.5 837.36,297.01 917.52,377.17 975.06,377.17 990.85,392.96 990.85,400.85 v1(1009,419)
  SIG1 w6.66: v1(1009,419) 1009,367 1071,305 1088.33,305 1268.79,124.54 1268.79,22.03 1256.67,9.91 1256.67,-94.59 1393.08,-231 1430.68,-231 1501.99,-302.31 1501.99,-317.59 1506.14,-321.74 v1(1506.14,-352.52)
  Bottom w5.66: v1(1506.14,-352.52) 1506.14,-365.93 1547.83,-407.61 1547.83,-424.17 1515.22,-456.78 EC1.92@1515.22,-528.32
CON1_PIN67: EC1.72 J1.67 | length 742.6
  Top Layer w5.66: J1.67@817.45,18.28 817.45,-15.83 870.46,-68.83 v1(913.83,-68.83)
  SIG1 w6.66: v1(913.83,-68.83) 930.83,-68.83 1187.18,-325.18 1187.18,-351.43 ; v1(1185,-370) 1187.17,-367.83 1187.17,-351.44
  Bottom w5.66: v1(1185,-370) 1187.33,-372.33 1187.33,-455.7 1199.66,-468.03 1199.66,-528.54 EC1.72@1199.85,-528.73
CON1_PIN68: EC1.90 J1.68 | length 1381.9
  Top Layer w5.66: J1.68@817.68,261.5 817.68,297.15 913.56,393.03 923.03,393.03 v1(925,395)
  SIG1 w6.66: v1(925,395) 1166.4,153.6 1166.4,-107.32 1343.72,-284.64 1416.64,-284.64 1444.02,-312.02 1444.02,-381.9 1452.4,-390.28 1452.4,-394.67 v1(1472.24,-414.51)
  Bottom w5.66: v1(1472.24,-414.51) 1471.14,-415.6 1471.14,-435.14 1483.72,-447.72 EC1.90@1483.72,-528.32
CON1_PIN69: EC1.70 J1.69 | length 901
  Top Layer w5.66: J1.69@797.99,18.5 797.99,51.9 818.43,72.34 917.63,72.34 1085.97,-96 v1(1145,-96)
  Bottom w5.66: v1(1145,-96) 1145,-323.12 1152,-330.12 1152,-368.91 1168.35,-385.27 EC1.70@1168.35,-528.73
CON1_PIN70: EC1.88 J1.70 | length 1446.3
  Top Layer w5.66: J1.70@797.99,261.5 797.99,296.62 921.37,420 945,420 v1(955,410)
  SIG1 w6.66: v1(955,410) 955.77,409.23 955.77,397.23 1231.33,121.67 1231.33,-95.33 1384.76,-248.76 1429.13,-248.76 1486,-305.64 1486,-369 v1(1470,-385)
  Bottom w5.66: EC1.88@1452.23,-528.32 1451.44,-527.54 1451.44,-403.56 v1(1470,-385)
CON1_PIN71: EC1.68 J1.71 | length 905.3
  Top Layer w5.66: J1.71@778.31,18.5 778.31,57.18 811.13,90 925.18,90 v1(1082.59,-67.41)
  Bottom w5.66: v1(1082.59,-67.41) 1082.59,-69.65 1093.84,-80.9 1093.84,-394.05 1137.27,-437.48 EC1.68@1137.27,-528.32
CON1_PIN72: EC1.86 J1.72 | length 1276.1
  Top Layer w5.66: J1.72@778.31,261.5 778.3,221.7 790,210 970,210 v1(993.58,233.58)
  SIG1 w6.66: v1(993.58,233.58) 995,232.17 995,-56.17 1273.83,-335 1371.32,-335 v1(1434.07,-397.88)
  Bottom w5.66: EC1.86@1421.14,-527.92 1421.14,-442.86 1434.13,-429.87 1434.13,-397.94 v1(1434.07,-397.88)
CON1_PIN73: EC1.91 J1.73 | length 1349.3
  Top Layer w5.66: J1.73@758.62,18.5 758.62,59.85 801.43,102.66 939.34,102.66 1119.66,-77.66 1240.44,-77.66 1272.57,-109.78 1401.4,-109.78 1410,-101.18 v1(1410,-100) ; EC1.91@1514.81,-528.73 1514.81,-425.03 1512.17,-422.39 1512.17,-398.05 1573.82,-336.39 v1(1573.82,-294)
  SIG1 w6.66: v1(1410,-100) 1449.08,-100 1573.82,-224.74 v1(1573.82,-294)
CON1_PIN74: EC1.95 J1.74 | length 1707.3
  Top Layer w5.66: J1.74@758.62,261.5 761.8,264.67 761.8,292.02 772.05,302.28 785.74,302.28 943.47,460 v1(1007.72,460) ; EC1.95@1578.21,-528.32 1578.21,-427.47 1578.17,-427.43 1578.17,-349.95 1595,-333.12 v1(1595,-330)
  SIG1 w6.66: v1(1007.72,460) 1010.79,460 1020.81,449.98 1031.11,449.98 1381.25,99.84 1381.25,-33.41 1412.84,-65 1560,-65 1628,-133 1628,-297 v1(1595,-330)
CON1_PIN75: EC1.89 J1.75 | length 1275.2
  Top Layer w5.66: J1.75@738.94,18.5 738.94,65.49 788.76,115.32 949.42,115.32 1129.74,-65 1268.66,-65 1274.66,-59 v1(1278,-59) ; EC1.89@1483.72,-528.32 1483.72,-428.24 1493.96,-418 1493.96,-380.87 1486.19,-373.1 1486.19,-344.13 v1(1520.32,-310)
  SIG1 w6.66: v1(1278,-59) 1518.15,-299.15 1518.15,-307.83 v1(1520.32,-310)
CON1_PIN85: EC1.45 J1.85 | length 1181.6
  Top Layer w5.66: J1.85@640.51,18.5 640.51,53.01 657,69.5 v1(657,110) ; EC1.45@664.83,-528.32 664.83,-467.15 654.59,-456.91 654.59,-418.16 759.19,-313.56 774.34,-313.56 926.44,-161.47 v1(926.44,-127.07)
  SIG1 w6.66: v1(657,110) 641.33,94.33 630.69,94.33 616,79.63 616,-75 687.51,-146.51 906.99,-146.51 v1(926.44,-127.07)
CON1_PIN87: EC1.43 J1.87 | length 976.7
  Top Layer w5.66: J1.87@620.83,18.5 621.39,19.07 621.39,58.62 635.52,72.75 v1(635.52,73.23) ; EC1.43@633.33,-528.32 633.33,-421.51 755.47,-299.38 770.63,-299.38 900,-170 900,-137.52 894,-131.52 v1(894,-128.18)
  SIG1 w6.66: v1(635.52,73.23) 635.52,-15.52 674.66,-54.66 697.66,-54.66 771.18,-128.18 v1(894,-128.18)
CON1_PIN97: C72.1 J1.97 R118.2 | length 860.3
  Top Layer w4: J1.97@522.4,18.5 518.4,22.51 518.4,47.05 518.06,47.39 518.06,59.5 v1(530.56,72) ; v1(694.06,575) 681.56,562.5 681.56,514.59 683.9,512.24 C72.1@709.54,512.24
  SIG1 w4.2: v1(530.56,72) 517.66,84.9 517.66,154.77 477.46,194.97 477.46,248.46 681.16,452.16 681.16,562.1 v1(694.06,575)
  Bottom w4: v1@694.06,574.02 681.56,561.52 681.56,517.54 683.9,515.2 R118.2@709.54,515.2
CON1_PIN98: C73.1 J1.98 R120.2 | length 824.8
  Top Layer w4: J1.98@522.4,261.5 518.4,257.49 518.4,232.95 518.06,232.61 518.06,218.5 v1(530.56,206) ; v1(828.94,575) 816.44,562.5 816.44,514.59 818.78,512.24 C73.1@844.42,512.24
  SIG1 w4.2: v1(530.56,206) 517.66,218.9 517.66,236.21 629.45,348 755.66,348 815.88,408.22 815.88,553.34 816.04,553.5 816.04,562.1 v1(828.94,575)
  Bottom w4: v1@828.94,574.02 816.44,561.52 816.44,517.54 818.78,515.2 R120.2@844.42,515.2
CON1_PIN99: C85.1 J1.99 R117.2 | length 860.3
  Top Layer w4: v1(494.56,72) 507.06,59.5 507.06,47.39 506.72,47.05 506.72,22.51 J1.99@502.72,18.5 ; C85.1@642.58,512.24 668.21,512.24 670.56,514.59 670.56,562.5 v1(658.06,575)
  SIG1 w4.2: v1(494.56,72) 507.46,84.9 507.46,150.54 474,184 467.26,190.74 467.26,252.68 670.96,456.38 670.96,562.1 v1(658.06,575)
  Bottom w4: R117.2@642.58,515.2 668.21,515.2 670.56,517.54 670.56,561.52 v1@658.06,574.02
CON1_PIN100: C74.1 J1.100 R119.2 | length 824.8
  Top Layer w4: v1(494.56,206) 507.06,218.5 507.06,232.61 506.72,232.95 506.72,257.49 J1.100@502.72,261.5 ; C74.1@777.46,512.24 803.1,512.24 805.44,514.59 805.44,562.5 v1(792.94,575)
  SIG1 w4.2: v1(494.56,206) 507.46,218.9 507.46,240.44 625.22,358.2 751.44,358.2 805.68,412.44 805.68,557.56 805.84,557.72 805.84,562.1 v1(792.94,575)
  Bottom w4: R119.2@777.46,515.2 803.1,515.2 805.44,517.54 805.44,561.52 v1@792.94,574.02
CON1_PIN101: C67.1 J1.101 R108.2 | length 1020.5
  Top Layer w4: v1@424.29,575 411.79,562.5 411.79,514.59 414.13,512.24 C67.1@439.77,512.24 ; v1(480.12,111.4) 480.12,111.35 468.61,99.83 468.61,72.95 478.69,62.87 478.69,47.39 479.03,47.05 479.03,22.51 J1.101@483.03,18.5
  Bottom w4: R108.2@436.96,513.94 411.32,513.94 408.98,516.28 408.98,560.26 v1(421.48,572.76) 408.27,585.96 408.27,593.02 398.02,603.27 370.71,603.27 338,570.56 338,343 361,320 361,287.03 361,245.22 361,131.49 421.49,71 454.12,71 467.56,84.44 467.56,98.84 v1(480.12,111.4)
CON1_PIN102: C71.1 J1.102 R116.2 | length 545.2
  Top Layer w4: J1.102@483.03,261.5 479.03,265.5 479.03,290.04 478.69,290.38 478.69,320.5 v1(491.19,333) ; v1(559.17,575) 546.67,562.5 546.67,514.59 549.02,512.24 C71.1@574.65,512.24
  SIG1 w4.2: v1(491.19,333) 489.87,333 478.29,344.58 478.29,348.06 518.2,387.98 518.2,484.7 546.27,512.78 546.27,562.1 v1(559.17,575)
  Bottom w4: v1(559.17,575) 546.67,562.5 546.67,518.52 549.02,516.18 R116.2@574.65,516.18
CON1_PIN103: C80.1 J1.103 R107.2 | length 1017.4
  Top Layer w4: C80.1@372.81,512.24 398.45,512.24 400.79,514.59 400.79,562.5 v1@388.29,575 ; v1(444,111.4) 447.79,111.4 453.2,105.99 454.14,105.99 456.49,103.65 456.49,69.51 467.69,58.31 467.69,47.39 467.35,47.05 467.35,22.51 J1.103@463.35,18.5
  Bottom w4: R107.2@370,513.94 395.64,513.94 397.98,516.28 397.98,560.26 v1(385.48,572.76) 397.27,584.55 397.27,588.46 393.46,592.27 375.27,592.27 349,566 349,347.56 372,324.56 372,287.03 372,245.22 372,136.04 379.57,128.47 382.6,125.44 386.49,125.44 396.62,135.57 400.51,135.57 404.4,131.68 404.4,127.79 394.27,117.66 394.27,113.77 398.16,109.88 402.05,109.88 412.3,120.13 416.19,120.13 420.08,116.25 420.08,112.36 409.83,102.1 409.83,98.21 419.02,89.02 426.04,82 449.56,82 456.56,89 456.56,98.84 v1(444,111.4)
CON1_PIN104: C84.1 J1.104 R115.2 | length 545.2
  Top Layer w4: v1(455.19,333) 467.69,320.5 467.69,290.38 467.35,290.04 467.35,265.5 J1.104@463.35,261.5 ; C84.1@507.7,512.24 533.33,512.24 535.67,514.59 535.67,562.5 v1(523.17,575)
  SIG1 w4.2: v1(455.19,333) 456.5,333 468.09,344.58 468.09,352.29 508,392.2 508,488.93 536.07,517 536.07,562.1 v1(523.17,575)
  Bottom w4: R115.2@507.7,516.18 533.33,516.18 535.67,518.52 535.67,562.5 v1(523.17,575)
CON1_PIN105: C65.1 J1.105 R104.2 | length 995.7
  Top Layer w4: v1(155.07,575) 142.57,562.5 142.57,514.59 144.92,512.24 C65.1@170.55,512.24 ; v1(346.54,106.46) 349.57,103.43 361.2,103.43 366.77,109 394.42,109 439.32,64.11 439.32,47.39 439.66,47.05 439.66,22.51 J1.105@443.66,18.5
  SIG1 w4.2: v1(155.07,575) 142.17,562.1 142.17,384.83 241.8,285.2 280.23,285.2 335.21,230.21 341.99,223.44 341.99,137.99 323.2,119.2 323.2,92.22 331.59,83.83 342.17,83.83 346.74,88.41 346.74,106.26 v1(346.54,106.46)
  Bottom w4: v1(155.07,575) 142.57,562.5 142.57,518.52 144.92,516.18 R104.2@170.55,516.18
CON1_PIN106: C66.1 J1.106 R106.2 | length 584.1
  Top Layer w4: v1(289.41,575) 276.91,562.5 276.91,514.59 279.25,512.24 C66.1@304.88,512.24 ; v1(401.12,376.12) 400.85,375.85 400.85,358.7 408.89,350.67 439.32,320.24 439.32,290.38 439.66,290.04 439.66,265.5 J1.106@443.66,261.5
  SIG1 w4.2: v1(289.41,575) 276.51,562.1 276.51,482.48 382.87,376.12 v1(401.12,376.12)
  Bottom w4: v1(289.41,575) 276.91,562.5 276.91,518.52 279.25,516.18 R106.2@304.88,516.18
CON1_PIN107: C78.1 J1.107 R103.2 | length 993.7
  Top Layer w4: C78.1@103.59,512.24 129.23,512.24 131.57,514.59 131.57,562.5 v1(119.07,575) ; v1(372,81) 368.98,84.02 368.98,95.66 371.32,98 389.87,98 428.32,59.55 428.32,47.39 427.98,47.05 427.98,22.51 J1.107@423.98,18.5
  SIG1 w4.2: v1(119.07,575) 131.97,562.1 131.97,380.6 149.18,363.39 237.58,275 276,275 331.79,219.21 331.79,142.21 313,123.42 313,88 327.37,73.63 346.39,73.63 353.95,81.19 371.81,81.19 v1(372,81)
  Bottom w4: R103.2@103.59,516.18 129.23,516.18 131.57,518.52 131.57,562.5 v1(119.07,575)
CON1_PIN108: C79.1 J1.108 R105.2 | length 583.5
  Top Layer w4: C79.1@237.93,512.24 263.56,512.24 265.91,514.59 265.91,562.5 v1(253.41,575) ; v1(375.66,350.66) 375.93,350.93 393.07,350.93 395.42,348.58 405,339 428.32,315.68 428.32,290.38 427.98,290.04 427.98,265.5 J1.108@423.98,261.5
  SIG1 w4.2: v1(253.41,575) 266.31,562.1 266.31,478.26 375.66,368.9 v1(375.66,350.66)
  Bottom w4: R105.2@237.93,516.18 263.56,516.18 265.91,518.52 265.91,562.5 v1(253.41,575)
CON1_PIN109: C69.1 J1.109 R112.2 | length 515.1
  Top Layer w4: J1.109@404.29,18.5 400.29,14.5 400.29,-10.04 399.95,-10.38 399.95,-28 425.17,-53.22 507.22,-53.22 521.44,-39 655.07,-39 672.96,-56.89 672.96,-64.76 681.19,-72.99 v1(685.46,-72.99) ; v1@685.46,-74.49 672.96,-86.99 672.96,-113.72 675.31,-116.06 R112.2@698.04,-116.06
  Bottom w4: v1(685.46,-72.99) 685.46,-75.65 673.11,-88 673.11,-117.66 675.46,-120 C69.1@698.19,-120
CON1_PIN110: C70.1 J1.110 R114.2 | length 899.7
  Top Layer w4: J1.110@404.29,261.5 400.29,257.49 400.29,232.95 399.95,232.61 399.95,216.05 427,189 645,189 650.85,194.85 650.85,198.16 v1(640.78,208.23) ; v1(828,-68) 828,-68.5 816.23,-80.27 816.23,-104.32 818.57,-106.66 R114.2@841.3,-106.66
  SIG1 w4.2: v1(640.78,208.23) 641.08,207.92 658.6,207.92 661.7,211.01 680.41,211.01 698.7,192.72 698.7,-15.18 710.32,-26.8 796.8,-26.8 818.2,-48.2 818.2,-58.2 v1(828,-68)
  Bottom w4: v1(828,-68) 828,-68.5 816.23,-80.27 816.23,-108.26 818.57,-110.6 C70.1@841.45,-110.6
CON1_PIN111: C82.1 J1.111 R111.2 | length 515.2
  Top Layer w4: J1.111@384.61,18.5 388.61,14.5 388.61,-10.04 388.95,-10.38 388.95,-32.56 420.61,-64.22 511.78,-64.22 526,-50 650.51,-50 661.96,-61.45 661.96,-64.76 653.74,-72.99 v1(649.46,-72.99) ; R111.2@636.89,-116.06 R111.2@637.04,-116.06 659.62,-116.06 661.96,-113.72 661.96,-86.99 v1@649.46,-74.49
  Bottom w4: C82.1@637.04,-120 659.77,-120 662.11,-117.66 662.11,-88 649.46,-75.35 v1(649.46,-72.99)
CON1_PIN112: C83.1 J1.112 R113.2 | length 898.8
  Top Layer w4: J1.112@384.61,261.5 388.61,257.49 388.61,232.95 388.95,232.61 388.95,211.49 414.22,186.22 422.44,178 649.45,178 653.39,181.94 665.4,181.94 v1(666,182.54) ; R113.2@780.15,-106.66 R113.2@780.3,-106.66 802.88,-106.66 805.23,-104.32 805.23,-78.81 794.41,-68 v1(792,-68)
  SIG1 w4.2: v1(666,182.54) 665.92,182.62 665.92,198.35 668.38,200.81 676.19,200.81 688.5,188.5 688.5,-19.4 706.1,-37 792.58,-37 806,-50.42 806,-63.84 803.54,-66.3 793.7,-66.3 v1(792,-68)
  Bottom w4: C83.1@780.3,-110.6 802.88,-110.6 805.23,-108.26 805.23,-78.81 794.41,-68 v1(792,-68)
CON1_PIN113: C64.1 J1.113 R102.2 | length 299.1
  Top Layer w4: R102.2@328.7,-126.06 305.97,-126.06 303.63,-123.72 303.63,-96.99 316.13,-84.49 v1(316.13,-82.99) 311.85,-82.99 303.63,-74.76 303.63,-71.45 311.18,-63.89 339.66,-63.89 360.58,-42.98 360.58,-10.38 360.92,-10.04 360.92,14.5 J1.113@364.92,18.5
  Bottom w4: v1(316.13,-82.99) 303.63,-95.49 303.63,-127.66 305.97,-130 C64.1@328.7,-130
CON1_PIN114: C68.1 J1.114 R110.2 | length 668
  Top Layer w4: v1(305,181) 305,182.09 315.4,192.49 342.63,192.49 360.58,210.44 360.58,232.61 360.92,232.95 360.92,257.49 J1.114@364.92,261.5 ; v1(497.28,-83.76) 497.28,-85.63 484.78,-98.13 484.78,-113.56 487.12,-115.91 R110.2@509.85,-115.91
  SIG1 w4.2: v1(305,181) 304.46,181 292.57,192.89 286.66,192.89 284.2,190.43 284.2,83 424.12,-56.92 470.49,-56.92 484.38,-70.8 484.38,-78.51 486.99,-81.12 494.64,-81.12 v1(497.28,-83.76)
  Bottom w4: v1(497.28,-83.76) 484.93,-96.11 484.93,-117.5 487.27,-119.84 C68.1@510,-119.84
CON1_PIN115: C77.1 J1.115 R101.2 | length 299.5
  Top Layer w4: R101.2@267.55,-126.06 290.28,-126.06 292.63,-123.72 292.63,-96.99 280.13,-84.49 v1(280.13,-82.99) 285,-82.99 290.51,-77.48 290.66,-77.48 293,-75.14 293,-66.52 306.63,-52.89 335.11,-52.89 349.58,-38.42 349.58,-10.38 349.24,-10.04 349.24,14.5 J1.115@345.24,18.5
  Bottom w4: C77.1@267.55,-130 290.28,-130 292.63,-127.66 292.63,-95.49 v1(280.13,-82.99)
CON1_PIN116: C81.1 J1.116 R109.2 | length 666.4
  Top Layer w4: v1(303.92,214.98) 315.4,203.49 338.07,203.49 349.58,215 349.58,232.61 349.24,232.95 349.24,257.49 J1.116@345.24,261.5 ; R109.2@448.85,-115.91 471.43,-115.91 473.78,-113.56 473.78,-98.13 461.28,-85.63 v1(461.28,-83.76)
  SIG1 w4.2: v1(303.92,214.98) 303.92,214.44 292.57,203.09 282.44,203.09 274,194.66 274,78.78 419.9,-67.12 466.27,-67.12 474.18,-75.03 474.18,-78.51 471.56,-81.12 463.92,-81.12 v1(461.28,-83.76)
  Bottom w4: C81.1@448.85,-119.84 471.58,-119.84 473.93,-117.5 473.93,-101.91 473.78,-101.76 473.78,-96.26 v1(461.28,-83.76)
CON1_PIN117: C62.1 J1.117 R98.2 | length 584.6
  Top Layer w4: R98.2@-5,-191.38 -27.79,-191.38 -30.14,-189.03 -30.14,-170.21 v1(-19.64,-159.71) -28.69,-150.66 -28.69,-147.34 -22.35,-141 34,-141 139,-36 305.8,-36 321.21,-20.6 321.21,-10.38 321.55,-10.04 321.55,14.5 J1.117@325.55,18.5
  Bottom w4: v1(-19.64,-159.71) -22.74,-159.71 -30.14,-167.11 -30.14,-174.98 -30.14,-192.97 -27.8,-195.31 C62.1@-5.13,-195.31
CON1_PIN118: C63.1 J1.118 R100.2 | length 683.8
  Top Layer w4: v1(177.43,-70) 177.43,-71.5 164.93,-84 164.93,-110.73 167.27,-113.07 R100.2@190,-113.07 ; J1.118@325.55,261.5 321.55,265.5 321.55,290.04 321.21,290.38 321.21,298 333.71,310.5 v1(333.71,314)
  Bottom w4: C63.1@190,-117.01 167.27,-117.01 164.93,-114.66 164.93,-82.5 v1(177.43,-70) 174.75,-67.32 167.65,-67.32 164.93,-64.6 164.93,-22.37 149,-6.44 149,98.4 275,224.4 275,224.51 321.21,270.72 321.21,301.5 v1(333.71,314)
